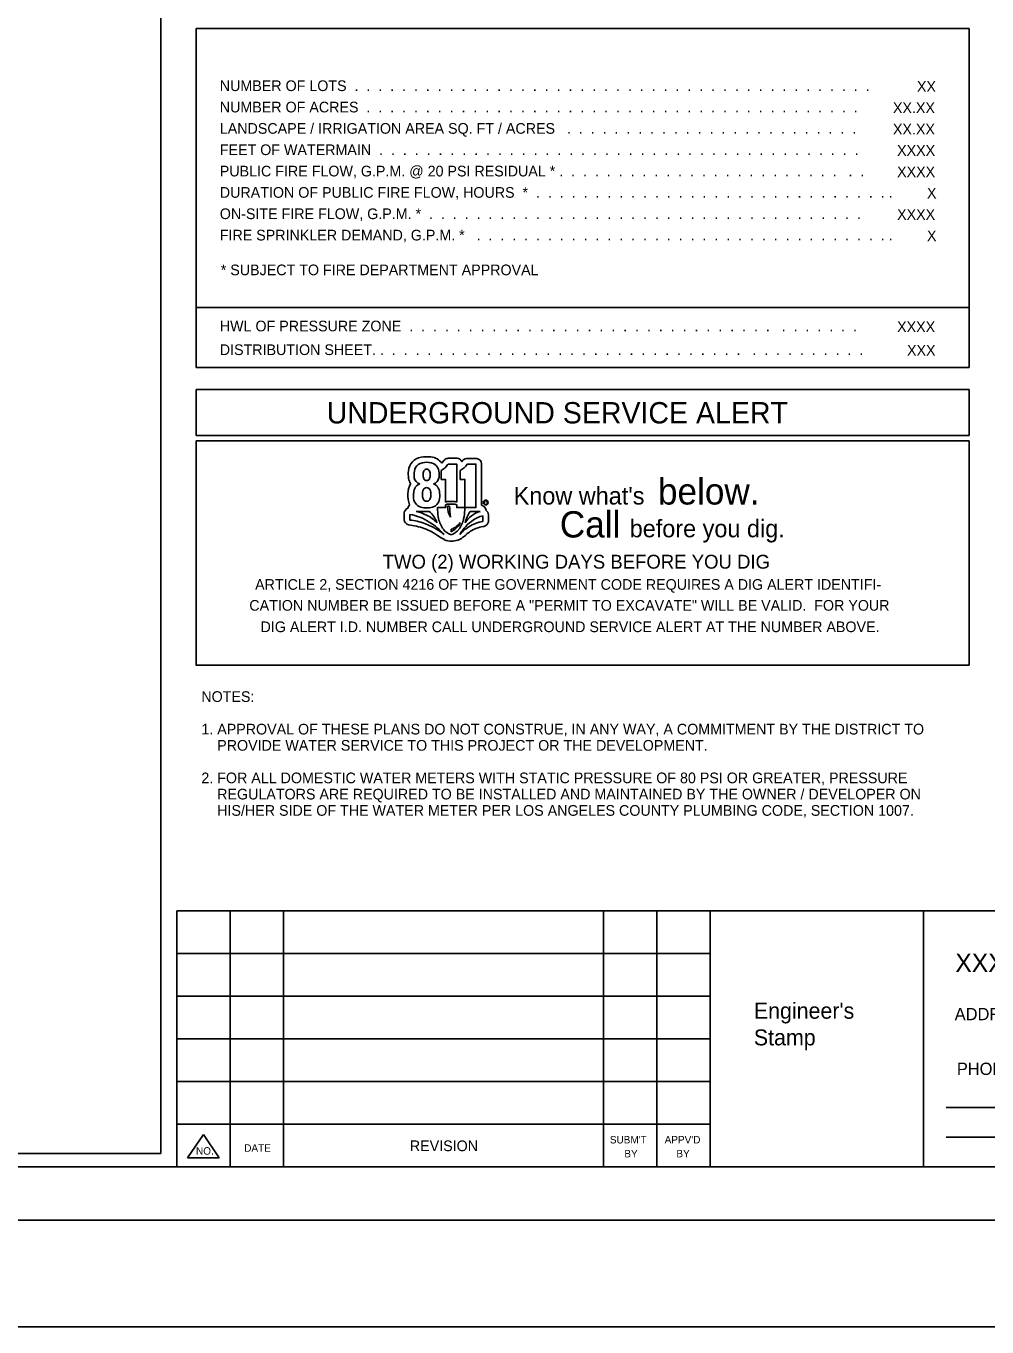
# Model space of a CAD drawing. Extents: x 837 to 1117, y 1316 to 1424.
# Drawn here: x 853.59 to 862.6, y 1398.24 to 1410.43 of the extents above; entities that cross this region are included whole.
import ezdxf

# ---------------------------------------------------------------- set-up
doc = ezdxf.new("R2010")
doc.units = 0
for name, color, linetype in [('0 (Construction)', 7, 'Continuous'), ('BASEMAP', 7, 'Continuous'), ('Border', 7, 'Continuous'), ('Call811-black', 7, 'Continuous'), ('LLINES', 7, 'Continuous'), ('TEXT', 7, 'Continuous')]:
    doc.layers.add(name, color=color, linetype=linetype)

msp = doc.modelspace()

# ---------------------------------------------------------------- linework, layer by layer
for p, q in [((855.187, 1406.544), (855.187, 1404.442)), ((862.435, 1406.544), (862.435, 1404.442))]:
    msp.add_line(p, q)
at = {"layer": '0 (Construction)'}
msp.add_lwpolyline([(841.77, 1422.24), (877.77, 1422.24), (877.77, 1398.24), (841.77, 1398.24)], close=True, dxfattribs=at)
at = {"layer": 'BASEMAP'}
for p, q in [((854.857, 1399.867), (854.857, 1420.065)), ((855.187, 1410.409), (862.435, 1410.409)), ((855.187, 1407.233), (855.187, 1410.409)), ((862.435, 1407.233), (862.435, 1410.409)), ((855.187, 1407.795), (862.435, 1407.795)), ((855.187, 1407.233), (862.435, 1407.233)), ((855.187, 1406.594), (855.187, 1407.026)), ((855.187, 1407.026), (862.435, 1407.026)), ((862.435, 1406.594), (862.435, 1407.026)), ((855.187, 1406.594), (862.435, 1406.594)), ((855.187, 1406.544), (862.435, 1406.544)), ((855.185, 1404.442), (862.435, 1404.442)), ((855.505, 1402.14), (855.505, 1399.74)), ((856.005, 1402.14), (856.005, 1399.74)), ((859.005, 1402.14), (859.005, 1399.74)), ((859.505, 1402.14), (859.505, 1399.74)), ((860.005, 1401.74), (855.005, 1401.74)), ((860.005, 1401.34), (855.005, 1401.34)), ((860.005, 1400.94), (855.005, 1400.94)), ((860.005, 1400.54), (855.005, 1400.54)), ((864.364, 1400.297), (862.218, 1400.297)), ((864.364, 1400.297), (862.218, 1400.297)), ((860.005, 1400.14), (855.005, 1400.14)), ((862.219, 1400.02), (865.041, 1400.02)), ((862.219, 1400.02), (865.041, 1400.02)), ((854.857, 1399.867), (843.678, 1399.867)), ((876.52, 1399.74), (843.52, 1399.74)), ((877.02, 1399.24), (843.02, 1399.24))]:
    msp.add_line(p, q, dxfattribs=at)
for points in [[(855.005, 1402.14), (860.005, 1402.14)], [(855.005, 1402.14), (855.005, 1399.74)], [(862.005, 1402.14), (860.005, 1402.14)], [(860.005, 1399.74), (860.005, 1402.14)], [(862.005, 1402.14), (865.255, 1402.14)], [(862.005, 1402.14), (862.005, 1399.74)]]:
    msp.add_lwpolyline(points, dxfattribs=at)
at = {"layer": 'Call811-black'}
for p, q in [((857.511, 1406.364), (857.49, 1406.336)), ((857.634, 1406.381), (857.547, 1406.381)), ((857.549, 1406.327), (857.63, 1406.327)), ((857.63, 1406.327), (857.63, 1405.97)), ((857.68, 1406.35), (857.678, 1406.35)), ((857.817, 1406.38), (857.723, 1406.38)), ((857.729, 1406.327), (857.81, 1406.327)), ((857.81, 1406.327), (857.81, 1405.92)), ((857.864, 1405.941), (857.864, 1406.33)), ((857.484, 1406.182), (857.484, 1406.268)), ((857.526, 1405.97), (857.526, 1406.187)), ((857.662, 1406.182), (857.662, 1406.268)), ((857.706, 1405.92), (857.706, 1406.187)), ((857.526, 1405.919), (857.526, 1405.945)), ((857.63, 1405.945), (857.63, 1405.919)), ((857.137, 1405.869), (857.137, 1405.805)), ((857.191, 1405.802), (857.191, 1405.856)), ((857.251, 1405.884), (857.374, 1405.884)), ((857.451, 1405.895), (857.451, 1405.919)), ((857.451, 1405.919), (857.526, 1405.919)), ((857.63, 1405.919), (857.705, 1405.919)), ((857.705, 1405.919), (857.705, 1405.895)), ((857.81, 1405.92), (857.706, 1405.92)), ((857.756, 1405.883), (857.849, 1405.883)), ((857.874, 1405.841), (857.874, 1405.789)), ((857.927, 1405.787), (857.927, 1405.852))]:
    msp.add_line(p, q, dxfattribs=at)
for points in [[(857.511, 1406.364), (857.49, 1406.336)], [(857.634, 1406.381), (857.547, 1406.381)], [(857.63, 1405.97), (857.63, 1406.327), (857.549, 1406.327)], [(857.68, 1406.35), (857.678, 1406.35)], [(857.706, 1405.92), (857.81, 1405.92), (857.81, 1406.327), (857.729, 1406.327)], [(857.817, 1406.38), (857.723, 1406.38)], [(857.864, 1405.941), (857.864, 1406.33)], [(857.484, 1406.268), (857.484, 1406.182)], [(857.526, 1406.187), (857.526, 1405.97)], [(857.662, 1406.268), (857.662, 1406.182)], [(857.706, 1406.187), (857.706, 1405.92)], [(857.451, 1405.895), (857.451, 1405.919), (857.526, 1405.919), (857.526, 1405.945)], [(857.63, 1405.945), (857.63, 1405.919), (857.705, 1405.919), (857.705, 1405.895)], [(857.137, 1405.869), (857.137, 1405.805)], [(857.191, 1405.856), (857.191, 1405.802)], [(857.251, 1405.884), (857.374, 1405.884)], [(857.756, 1405.883), (857.849, 1405.883)], [(857.874, 1405.841), (857.874, 1405.789)], [(857.927, 1405.787), (857.927, 1405.852)], [(857.578, 1405.693), (857.578, 1405.717)]]:
    msp.add_lwpolyline(points, dxfattribs=at)
for radius in [0.0224, 0.0224, 0.0191, 0.0191]:
    msp.add_circle((857.902, 1405.967), radius, dxfattribs=at)
for centre, radius, start, end in [((857.321, 1406.252), 0.143, 99.999, 175.1926), ((857.321, 1406.252), 0.143, 99.999, 175.1926), ((857.323, 1406.25), 0.0905, 126.3161, 173.2477), ((857.323, 1406.25), 0.0905, 126.3161, 173.2477), ((857.344, 1406.202), 0.142, 87.8118, 121.4594), ((857.344, 1406.202), 0.142, 87.8118, 121.4594), ((857.349, 1406.078), 0.318, 82.8327, 99.5813), ((857.349, 1406.078), 0.318, 82.8327, 99.5813), ((857.353, 1406.203), 0.141, 58.4897, 91.5654), ((857.353, 1406.203), 0.141, 58.4897, 91.5654), ((857.372, 1406.246), 0.149, 37.4108, 83.4439), ((857.372, 1406.246), 0.149, 37.4108, 83.4439), ((857.373, 1406.25), 0.0905, 6.7523, 53.6839), ((857.373, 1406.25), 0.0905, 6.7523, 53.6839), ((857.426, 1406.397), 0.141, 294.2543, 330.2691), ((857.426, 1406.397), 0.141, 294.2543, 330.2691), ((857.548, 1406.332), 0.0484, 90.4592, 139.5917), ((857.548, 1406.332), 0.0484, 90.4592, 139.5917), ((857.63, 1406.328), 0.0532, 25.4835, 85.607), ((857.63, 1406.328), 0.0532, 25.4835, 85.607), ((857.603, 1406.403), 0.147, 293.5734, 328.8767), ((857.603, 1406.403), 0.147, 293.5734, 328.8767), ((857.728, 1406.327), 0.0538, 94.7078, 153.6211), ((857.728, 1406.327), 0.0538, 94.7078, 153.6211), ((857.81, 1406.327), 0.0534, 2.8738, 82.3381), ((857.81, 1406.327), 0.0534, 2.8738, 82.3381), ((857.431, 1406.229), 0.255, 172.2103, 188.1816), ((857.431, 1406.229), 0.255, 172.2103, 188.1816), ((857.311, 1406.212), 0.133, 188.1816, 212.2335), ((857.311, 1406.212), 0.133, 188.1816, 212.2335), ((857.393, 1406.229), 0.163, 168.7247, 190.4792), ((857.393, 1406.229), 0.163, 168.7247, 190.4792), ((857.302, 1406.209), 0.07, 187.8977, 254.9735), ((857.302, 1406.209), 0.07, 187.8977, 254.9735), ((857.446, 1406.227), 0.131, 172.09, 185.2177), ((857.446, 1406.227), 0.131, 172.09, 185.2177), ((857.378, 1406.236), 0.0618, 152.1584, 172.0655), ((857.378, 1406.236), 0.0618, 152.1584, 172.0655), ((857.384, 1406.217), 0.0679, 181.9453, 206.7716), ((857.384, 1406.217), 0.0679, 181.9453, 206.7716), ((857.347, 1406.252), 0.0271, 87.8996, 151.6932), ((857.347, 1406.252), 0.0271, 87.8996, 151.6932), ((857.348, 1406.201), 0.0292, 209.2686, 270.3024), ((857.348, 1406.201), 0.0292, 209.2686, 270.3024), ((857.349, 1406.252), 0.0272, 28.3588, 93.3211), ((857.349, 1406.252), 0.0272, 28.3588, 93.3211), ((857.348, 1406.201), 0.0293, 271.4639, 330.7182), ((857.348, 1406.201), 0.0293, 271.4639, 330.7182), ((857.319, 1406.236), 0.0618, 7.9345, 27.8416), ((857.319, 1406.236), 0.0618, 7.9345, 27.8416), ((857.313, 1406.217), 0.0679, 333.2284, 358.0547), ((857.313, 1406.217), 0.0679, 333.2284, 358.0547), ((857.25, 1406.227), 0.131, 354.7823, 7.91), ((857.25, 1406.227), 0.131, 354.7823, 7.91), ((857.394, 1406.209), 0.07, 285.0265, 352.1023), ((857.394, 1406.209), 0.07, 285.0265, 352.1023), ((857.304, 1406.229), 0.163, 349.5208, 11.2753), ((857.304, 1406.229), 0.163, 349.5208, 11.2753), ((857.494, 1406.27), 0.0887, 263.562, 290.9659), ((857.494, 1406.27), 0.0887, 263.562, 290.9659), ((857.672, 1406.28), 0.0988, 263.8986, 289.847), ((857.672, 1406.28), 0.0988, 263.8986, 289.847), ((857.35, 1406.048), 0.178, 148.69, 179.574), ((857.35, 1406.048), 0.178, 148.69, 179.574), ((857.44, 1406.031), 0.215, 173.4284, 191.4963), ((857.44, 1406.031), 0.215, 173.4284, 191.4963), ((857.33, 1406.054), 0.103, 145.6767, 179.0533), ((857.33, 1406.054), 0.103, 145.6767, 179.0533), ((857.309, 1406.068), 0.0779, 108.4812, 145.0863), ((857.309, 1406.068), 0.0779, 108.4812, 145.0863), ((857.465, 1406.044), 0.156, 172.09, 185.2177), ((857.465, 1406.044), 0.156, 172.09, 185.2177), ((857.383, 1406.055), 0.0737, 152.1584, 172.0655), ((857.383, 1406.055), 0.0737, 152.1584, 172.0655), ((857.346, 1406.074), 0.0323, 87.8996, 151.6932), ((857.346, 1406.074), 0.0323, 87.8996, 151.6932), ((857.349, 1406.074), 0.0324, 28.3588, 93.3211), ((857.349, 1406.074), 0.0324, 28.3588, 93.3211), ((857.313, 1406.055), 0.0737, 7.9345, 27.8416), ((857.313, 1406.055), 0.0737, 7.9345, 27.8416), ((857.231, 1406.044), 0.156, 354.7823, 7.91), ((857.231, 1406.044), 0.156, 354.7823, 7.91), ((857.388, 1406.068), 0.0779, 34.9137, 71.5188), ((857.388, 1406.068), 0.0779, 34.9137, 71.5188), ((857.366, 1406.054), 0.103, 0.9467, 34.3233), ((857.366, 1406.054), 0.103, 0.9467, 34.3233), ((857.256, 1406.031), 0.215, 348.5037, 6.5716), ((857.256, 1406.031), 0.215, 348.5037, 6.5716), ((857.397, 1406.033), 0.226, 175.7868, 203.0663), ((857.397, 1406.033), 0.226, 175.7868, 203.0663), ((857.211, 1405.912), 0.0386, 122.909, 178.0418), ((857.211, 1405.912), 0.0386, 122.909, 178.0418), ((857.322, 1406.014), 0.0963, 195.5875, 233.3016), ((857.322, 1406.014), 0.0963, 195.5875, 233.3016), ((857.332, 1406.037), 0.12, 236.207, 265.1802), ((857.332, 1406.037), 0.12, 236.207, 265.1802), ((857.39, 1406.032), 0.0809, 181.9453, 206.7716), ((857.39, 1406.032), 0.0809, 181.9453, 206.7716), ((857.348, 1406.013), 0.0348, 209.2686, 270.3024), ((857.348, 1406.013), 0.0348, 209.2686, 270.3024), ((857.347, 1406.013), 0.0349, 271.4639, 330.7182), ((857.347, 1406.013), 0.0349, 271.4639, 330.7182), ((857.365, 1406.037), 0.12, 274.8198, 303.793), ((857.365, 1406.037), 0.12, 274.8198, 303.793), ((857.306, 1406.032), 0.0809, 333.2284, 358.0547), ((857.306, 1406.032), 0.0809, 333.2284, 358.0547), ((857.374, 1406.014), 0.0963, 306.6984, 344.4125), ((857.374, 1406.014), 0.0963, 306.6984, 344.4125), ((857.55, 1405.922), 0.0538, 98.3212, 116.1927), ((857.55, 1405.922), 0.0538, 98.3212, 116.1927), ((857.55, 1405.897), 0.0538, 98.3212, 116.1927), ((857.55, 1405.897), 0.0538, 98.3212, 116.1927), ((857.575, 1405.782), 0.196, 88.3567, 99.6507), ((857.575, 1405.782), 0.196, 88.3567, 99.6507), ((857.575, 1405.757), 0.196, 88.3567, 99.6507), ((857.575, 1405.757), 0.196, 88.3567, 99.6507), ((857.558, 1405.897), 0.0372, 82.0234, 112.2206), ((858.152, 1405.924), 0.588, 179.0296, 189.1158), ((857.582, 1405.792), 0.186, 80.2121, 90.547), ((857.582, 1405.792), 0.186, 80.2121, 90.547), ((857.582, 1405.767), 0.186, 80.2121, 90.547), ((857.582, 1405.767), 0.186, 80.2121, 90.547), ((857.606, 1405.922), 0.0538, 63.8073, 81.6788), ((857.606, 1405.922), 0.0538, 63.8073, 81.6788), ((857.606, 1405.897), 0.0538, 63.8073, 81.6788), ((857.606, 1405.897), 0.0538, 63.8073, 81.6788), ((857.847, 1405.88), 0.0631, 53.7627, 75.1967), ((857.847, 1405.88), 0.0631, 53.7627, 75.1967), ((857.191, 1405.863), 0.0539, 110.5293, 173.0158), ((857.191, 1405.863), 0.0539, 110.5293, 173.0158), ((857.095, 1405.339), 0.525, 57.9733, 79.5163), ((857.095, 1405.339), 0.525, 57.9733, 79.5163), ((857.156, 1405.483), 0.412, 62.33, 76.6551), ((857.156, 1405.483), 0.412, 62.33, 76.6551), ((857.346, 1406.102), 0.186, 262.4451, 271.0167), ((857.346, 1406.102), 0.186, 262.4451, 271.0167), ((857.205, 1405.552), 0.329, 43.0467, 64.4523), ((857.205, 1405.552), 0.329, 43.0467, 64.4523), ((857.351, 1406.096), 0.18, 269.5148, 277.6277), ((857.351, 1406.096), 0.18, 269.5148, 277.6277), ((857.197, 1405.689), 0.263, 19.3184, 47.9077), ((857.197, 1405.689), 0.263, 19.3184, 47.9077), ((857.815, 1405.898), 0.364, 180.4178, 193.2572), ((857.815, 1405.898), 0.364, 180.4178, 193.2572), ((857.679, 1405.855), 0.222, 190.4857, 218.6347), ((857.679, 1405.855), 0.222, 190.4857, 218.6347), ((857.739, 1405.929), 0.195, 179.2441, 210.2904), ((857.477, 1405.855), 0.222, 321.3653, 349.5143), ((857.477, 1405.855), 0.222, 321.3653, 349.5143), ((857.341, 1405.898), 0.364, 346.7428, 359.5822), ((857.341, 1405.898), 0.364, 346.7428, 359.5822), ((857.921, 1405.645), 0.249, 106.8433, 148.53), ((857.989, 1405.718), 0.285, 144.6348, 168.4777), ((857.921, 1405.645), 0.249, 106.8433, 148.53), ((857.989, 1405.718), 0.285, 144.6348, 168.4777), ((857.915, 1405.631), 0.214, 100.9877, 126.326), ((857.915, 1405.631), 0.214, 100.9877, 126.326), ((857.846, 1405.886), 0.0594, 7.3834, 48.7359), ((857.846, 1405.886), 0.0594, 7.3834, 48.7359), ((857.877, 1405.852), 0.0499, 0.2357, 57.1812), ((857.877, 1405.852), 0.0499, 0.2357, 57.1812), ((857.19, 1405.809), 0.0528, 183.4717, 256.8514), ((857.19, 1405.809), 0.0528, 183.4717, 256.8514), ((856.758, 1403.118), 2.672, 79.3174, 80.9479), ((856.758, 1403.118), 2.672, 79.3174, 80.9479), ((857.139, 1405.272), 0.533, 69.1311, 84.5007), ((857.139, 1405.272), 0.533, 69.1311, 84.5007), ((857.12, 1405.159), 0.6, 62.6567, 77.1974), ((857.12, 1405.159), 0.6, 62.6567, 77.1974), ((857.119, 1405.179), 0.627, 50.9726, 70.3844), ((857.119, 1405.179), 0.627, 50.9726, 70.3844), ((857.063, 1405.274), 0.597, 41.0274, 58.6813), ((857.063, 1405.274), 0.597, 41.0274, 58.6813), ((856.41, 1404.073), 1.896, 56.1356, 58.6515), ((856.41, 1404.073), 1.896, 56.1356, 58.6515), ((857.621, 1405.806), 0.147, 217.9711, 252.8236), ((857.621, 1405.806), 0.147, 217.9711, 252.8236), ((857.548, 1405.835), 0.122, 284.3512, 313.9705), ((857.493, 1405.87), 0.196, 295.7354, 319.9002), ((857.535, 1405.806), 0.147, 287.1764, 322.0289), ((857.535, 1405.806), 0.147, 287.1764, 322.0289), ((857.385, 1406.015), 0.365, 312.7475, 319.6368), ((857.57, 1405.808), 0.0975, 318.3348, 342.4149), ((858.026, 1405.455), 0.423, 124.3323, 149.8558), ((858.026, 1405.455), 0.423, 124.3323, 149.8558), ((857.945, 1405.422), 0.376, 122.1554, 139.2439), ((857.945, 1405.422), 0.376, 122.1554, 139.2439), ((857.942, 1405.416), 0.335, 122.9567, 131.4897), ((857.942, 1405.416), 0.335, 122.9567, 131.4897), ((857.914, 1405.489), 0.302, 97.6832, 123.9821), ((857.914, 1405.489), 0.302, 97.6832, 123.9821), ((857.92, 1405.452), 0.293, 110.3424, 123.2327), ((857.92, 1405.452), 0.293, 110.3424, 123.2327), ((857.932, 1405.407), 0.339, 99.6589, 109.4788), ((857.932, 1405.407), 0.339, 99.6589, 109.4788), ((857.867, 1405.81), 0.0698, 276.8288, 293.6655), ((857.867, 1405.81), 0.0698, 276.8288, 293.6655), ((857.876, 1405.795), 0.0518, 290.7825, 351.1469), ((857.876, 1405.795), 0.0518, 290.7825, 351.1469), ((857.609, 1405.833), 0.234, 232.4217, 246.1444), ((857.609, 1405.833), 0.234, 232.4217, 246.1444), ((857.577, 1405.751), 0.147, 244.4852, 271.9359), ((857.577, 1405.751), 0.147, 244.4852, 271.9359), ((857.582, 1405.787), 0.182, 269.938, 287.1165), ((857.582, 1405.787), 0.182, 269.938, 287.1165), ((857.563, 1405.809), 0.21, 290.4356, 305.7025), ((857.563, 1405.809), 0.21, 290.4356, 305.7025), ((857.489, 1405.922), 0.345, 304.793, 312.2432), ((857.489, 1405.922), 0.345, 304.793, 312.2432)]:
    msp.add_arc(centre, radius, start, end, dxfattribs=at)
at = {"layer": 'LLINES'}
for p, q in [((855.255, 1400.044), (855.107, 1399.825)), ((855.255, 1400.044), (855.402, 1399.825)), ((855.107, 1399.825), (855.402, 1399.825))]:
    msp.add_line(p, q, dxfattribs=at)

# ---------------------------------------------------------------- texts
for s, p in [("Engineer's", (860.416, 1401.129)), ('Stamp', (860.416, 1400.879))]:
    msp.add_text(s, height=0.15).set_placement(p)
at = {"layer": 'BASEMAP'}
for s, p in [('ADDRESS', (862.299, 1401.115)), ('PHONE: ', (862.319, 1400.602))]:
    msp.add_text(s, height=0.1152, dxfattribs=at).set_placement(p)
at = {"layer": 'Border'}
for s, height, p in [('below. ', 0.2464, (859.517, 1405.948)), ("Know what's", 0.16429, (858.164, 1405.948)), ('Call', 0.2464, (858.597, 1405.639)), ('before you dig.', 0.16429, (859.252, 1405.641))]:
    msp.add_text(s, height=height, dxfattribs=at).set_placement(p)
at = {"layer": 'Call811-black'}
msp.add_text('R', height=0.0236, dxfattribs=at).set_placement((857.89, 1405.955))
at = {"layer": 'LLINES'}
for s, height, p in [('NUMBER OF LOTS  .  .  .  .  .  .  .  .  .  .  .  .  .  .  .  .  .  .  .  .  .  .  .  .  .  .  .  .  .  .  .  .  .  .  .  .  .  .  .  .  .  .  .  .', 0.1, (855.409, 1409.823)), ('XX', 0.1, (861.945, 1409.816)), ('NUMBER OF ACRES  .  .  .  .  .  .  .  .  .  .  .  .  .  .  .  .  .  .  .  .  .  .  .  .  .  .  .  .  .  .  .  .  .  .  .  .  .  .  .  .  .  .', 0.1, (855.409, 1409.623)), ('XX.XX', 0.1, (861.72, 1409.616)), ('LANDSCAPE / IRRIGATION AREA SQ. FT / ACRES   .  .  .  .  .  .  .  .  .  .  .  .  .  .  .  .  .  .  .  .  .  .  .  .  .', 0.1, (855.409, 1409.423)), ('XX.XX', 0.1, (861.72, 1409.416)), ('FEET OF WATERMAIN  .  .  .  .  .  .  .  .  .  .  .  .  .  .  .  .  .  .  .  .  .  .  .  .  .  .  .  .  .  .  .  .  .  .  .  .  .  .  .  .  .', 0.1, (855.409, 1409.223)), ('XXXX', 0.1, (861.759, 1409.216)), ('PUBLIC FIRE FLOW, G.P.M. @ 20 PSI RESIDUAL * .  .  .  .  .  .  .  .  .  .  .  .  .  .  .  .  .  .  .  .  .  .  .  .   .  .', 0.1, (855.409, 1409.023)), ('XXXX', 0.1, (861.759, 1409.016)), ('DURATION OF PUBLIC FIRE FLOW, HOURS  *  .  .  .  .  .  .  .  .  .  .  .  .  .  .  .  .  .  .  .  .  .  .  .  .  .  .  .  .  .  . .', 0.1, (855.409, 1408.823)), ('X', 0.1, (862.039, 1408.816)), ('ON-SITE FIRE FLOW, G.P.M. *  .  .  .  .  .  .  .  .  .  .  .  .  .  .  .  .  .  .  .  .  .  .  .  .  .  .  .  .  .  .  .  .  .  .  .  .  .', 0.1, (855.409, 1408.623)), ('XXXX', 0.1, (861.759, 1408.616)), ('FIRE SPRINKLER DEMAND, G.P.M. *   .  .  .  .  .  .  .  .  .  .  .  .  .  .  .  .  .  .  .  .  .  .  .  .  .  .  .  .  .  .  .  .  .  .  . .', 0.1, (855.409, 1408.423)), ('X', 0.1, (862.039, 1408.416)), ('* SUBJECT TO FIRE DEPARTMENT APPROVAL', 0.1, (855.418, 1408.097)), ('HWL OF PRESSURE ZONE  .  .  .  .  .  .  .  .  .  .  .  .  .  .  .  .  .  .  .  .  .  .  .  .  .  .  .  .  .  .  .   .  .  .  .  .  .  .  ', 0.1, (855.409, 1407.571)), ('XXXX', 0.1, (861.759, 1407.564)), ('DISTRIBUTION SHEET. .  .  .  .  .  .  .  .  .  .  .  .  .  .  .  .  .  .  .  .  .  .  .  .  .  .  .  .  .  .  .   .  .  .  .  .  .  .  .  .  .', 0.1, (855.409, 1407.349)), ('XXX', 0.1, (861.852, 1407.343)), ('UNDERGROUND SERVICE ALERT', 0.2, (856.411, 1406.708)), ('REVISION', 0.1, (857.191, 1399.888)), ("SUBM'T", 0.07, (859.066, 1399.96)), ("APPV'D", 0.07, (859.58, 1399.96)), ('NO.', 0.07, (855.186, 1399.855)), ('DATE', 0.07, (855.638, 1399.882)), ('BY', 0.07, (859.202, 1399.829)), ('BY', 0.07, (859.69, 1399.83))]:
    msp.add_text(s, height=height, dxfattribs=at).set_placement(p)
at = {"layer": 'TEXT'}
for s, height, p in [('TWO (2) WORKING DAYS BEFORE YOU DIG', 0.13, (856.936, 1405.347)), ('ARTICLE 2, SECTION 4216 OF THE GOVERNMENT CODE REQUIRES A DIG ALERT IDENTIFI-', 0.1, (855.74, 1405.149)), ('CATION NUMBER BE ISSUED BEFORE A "PERMIT TO EXCAVATE" WILL BE VALID.  FOR YOUR', 0.1, (855.686, 1404.953)), ('DIG ALERT I.D. NUMBER CALL UNDERGROUND SERVICE ALERT AT THE NUMBER ABOVE.', 0.1, (855.791, 1404.752)), ('NOTES:', 0.1, (855.236, 1404.098)), ('1. APPROVAL OF THESE PLANS DO NOT CONSTRUE, IN ANY WAY, A COMMITMENT BY THE DISTRICT TO', 0.1, (855.236, 1403.793)), ('    PROVIDE WATER SERVICE TO THIS PROJECT OR THE DEVELOPMENT.', 0.1, (855.236, 1403.641)), ('2. FOR ALL DOMESTIC WATER METERS WITH STATIC PRESSURE OF 80 PSI OR GREATER, PRESSURE ', 0.1, (855.236, 1403.336)), ('    REGULATORS ARE REQUIRED TO BE INSTALLED AND MAINTAINED BY THE OWNER / DEVELOPER ON', 0.1, (855.236, 1403.184)), ('    HIS/HER SIDE OF THE WATER METER PER LOS ANGELES COUNTY PLUMBING CODE, SECTION 1007.', 0.1, (855.236, 1403.031)), ('XXXXX ENGINEERING', 0.1728, (862.305, 1401.567))]:
    msp.add_text(s, height=height, dxfattribs=at).set_placement(p)

doc.saveas('drawing.dxf')
